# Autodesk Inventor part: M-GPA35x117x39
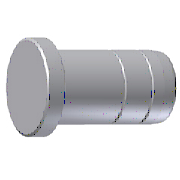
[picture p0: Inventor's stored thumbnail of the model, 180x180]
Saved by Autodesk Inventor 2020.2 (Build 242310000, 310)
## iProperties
Manager: www.cadconsulting.pl
Company: Fabian Stasiak CAD Consulting
Created: 2014-02
Part Number: M-GPA35x117x39
Material: SUJ 2
Description: GUIDE PIN
Document SubType Name: Modeling
Designer: F.Stasiak
Standard Revision: 1
Manufacturer: FUTABA
Language: pl-PL
Size Designation: 35x117x39
Categories: <MemberInstance><Categories><Category DisplayName="Forma wtryskowa" InternalName="349578f2-f4d4-4954-8c09-8e99297a61c0" Mnemonic="MOLD"><Category DisplayName="K
Mass: 12.6115 g
Surface Area: 36.5267 cm^2
Volume: 12.6115 cm^3
Density: 7.85 g/cm^3
Appearance: Domyślna
Catalog Web Link: www.expertbooks.pl
IsCustomPart: 0
Author: F.Stasiak
Subject: Zbiór ćwiczeń. Autodesk Inventor 2020. Kurs Professional
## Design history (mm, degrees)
sketch "Sketch1"
  geometry: L1 (0, -114.465)-(0, 26.077) reference; L2 (0, 8)-(20, 8); L3 (20, 8)-(20, 0); L4 (20, 0)-(17, 0); L5 (17, 0)-(17, -1.5); L6 (17, -1.5)-(17.5, -1.5); L7 (17.5, -1.5)-(17.5, -31); L8 (17.5, -31)-(17.5, -31); L9 (17.5, -31)-(17.5, -102); L10 (17.5, -102)-(17.047, -107.174); L11 (15.055, -109)-(0, -109); L12 (0, 8)-(0, -109); A1 r 2 centre (15.055, -107) between (15.055, -109) and (17.047, -107.174); 2 further points
  constraints: 30 end point, 5 perpendicular, 4 parallel, 4 point on line, 2 point on circle, 2 tangent, 1 centre point, 1 collinear, 1 horizontal alignment
  dimensions: "d0" = 40 diameter of L3 L1 (= D); "d2" = 1.5 distance of L4.end L5.end; "d3" = 8 distance between parallel lines of L4 L2 (= H_); "d5" = 0.5 distance between parallel lines of L7 L5; "d6" = 39 distance between parallel lines of L2 L8 (= N_); "d7" = 35 diameter of L7 L1 (= d1); "d8" = 117 distance between parallel lines of L2 L11 (= L); "d9" = 35 diameter of L9 L1 (= d_); "d10" = 7 vertical distance of L9.end point (16.888, -109) (= E_); "d11" = 5 deg angle of L9 L10; "d12" = 2 radius of A1
revolve "Revolution1" sketch "Sketch1" stored, may be unused: angle "d18" = 90 deg
sketch "Sketch2"
  geometry: L1 (17.5, -1.5)-(17.5, -102) reference; C1 r 0.5 at (17.5, -24)
  constraints: 1 centre point, 1 point on line
  dimensions: "d31" = 1 diameter of C1; "d68" = 78 distance of L1.end C1.centre (derived)
coil "Coil1" sketch "Sketch2" pitch "d37" = 26 (= P); turns "d39" = 3; dims "d38" = 58.5 (derived), "d40" = 0, angle "d41" = 90 deg, angle "d42" = 90 deg, "d43" = 0, "d44" = 0
sketch "Sketch3"
  geometry: L1 (0.5, 0)-(-0.5, 0); A1 r 0.5 centre (0, 0) between (-0.5, 0) and (0.5, 0) reference; A2 r 0.5 centre (0, 0) between (-0.5, 0) and (0.5, 0)
  constraints: 2 end point, 2 point on circle, 1 centre point, 1 coincident, 1 horizontal, 1 midpoint
  dimensions: "d71" = 0.5 radius of A2
revolve "Revolution2" sketch "Sketch3" stored, may be unused: angle "d54" = 90 deg
sketch "Sketch4"
  geometry: L1 (-0.5, 0)-(0.5, 0); A1 r 0.5 centre (0, 0) between (-0.5, 0) and (0.5, 0) reference; A2 r 0.5 centre (0, 0) between (-0.5, 0) and (0.5, 0)
  constraints: 2 end point, 2 point on circle, 1 centre point, 1 coincident, 1 horizontal, 1 midpoint
  dimensions: "d72" = 0.5 radius of A2
revolve "Revolution3" sketch "Sketch4" stored, may be unused: angle "d55" = 90 deg
sketch "Sketch5"
  geometry: L1 (17.5, -1.5)-(17.5, -102) reference; L2 (0, -106.8)-(0, 17.8) reference; C1 r 0.5 at (17.5, -33.75); C2 r 0.5 at (17.5, -72.75); 1 further point
  constraints: 2 centre point, 2 point on line, 1 equal radius
  dimensions: "d59" = 1 diameter of C1; "d61" = 39 distance of C2.centre C1.centre (derived); "d69" = 29.25 distance of L1.end C2.centre (derived)
revolve "Revolution4" sketch "Sketch5" stored, may be unused: angle "d70" = 90 deg
fillet "Fillet1" dims "d63" = 0.3
chamfer "Chamfer1" distance "d64" = 0.5; stored, may be unused: second distance "d65" = 2, angle "d66" = 45 deg
body "Solid1"
other parameters: "d_" = 35 [user parameter; used in 1 equation term], "L" = 117 [user parameter; used in 1 equation term], "d1" = 35 [user parameter; used in 1 equation term], "H_" = 8 [user parameter; used in 1 equation term], "D" = 40 [user parameter; used in 1 equation term], "N_" = 39 [user parameter; used in 1 equation term], "S_" = 52 [user parameter], "P" = 26 [user parameter; used in 1 equation term], "d56" = 0, "d58" = 0, "E_" = 7 [user parameter; used in 1 equation term], "d67" = 0
